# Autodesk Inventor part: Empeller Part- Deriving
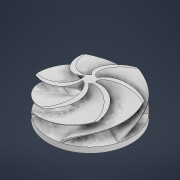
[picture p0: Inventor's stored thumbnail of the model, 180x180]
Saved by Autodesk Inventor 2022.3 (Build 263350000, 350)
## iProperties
Created: 2022-11
Part Number: Empeller Part- Deriving
Material: Generic
Document SubType Name: Modeling
Designer: LENOVO
Density: 1 g/cm^3
Appearance: Default
Author: LENOVO
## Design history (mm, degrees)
derived "Empeller-Sweep.ipt"
  workaxis "Work Axis1"
feature "Solid1::Empeller-Sweep.ipt" dims "d0" = 10
tag "TaggingFeature1"
body "Solid1"
